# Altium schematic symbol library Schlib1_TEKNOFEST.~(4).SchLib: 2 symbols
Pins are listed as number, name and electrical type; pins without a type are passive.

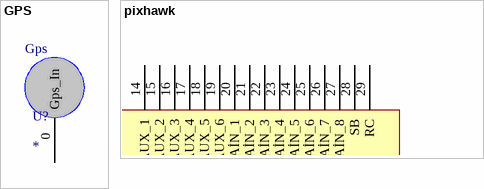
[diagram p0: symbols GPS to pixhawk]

## GPS
designator U?
pins: 0 Gps_In

## pixhawk
designator U?
pins: 0 SSR, 1 Switch, 2 Telem1, 3 Telem2, 4 USB, 5 SPI, 6 POWER, 7 BUZZER, 8 SERİAL 4/5, 9 GPS, 10 CAN, 11 I2C, 12 ADC3.3V, 13 ADC6.6V, 14 PWM AUX_1, 15 PWM AUX_2, 16 PWM AUX_3, 17 PWM AUX_4, 18 PWM AUX_5, 19 PWM AUX_6, 20 PWM MAİN_1, 21 PWM MAİN_2, 22 PWM MAİN_3, 23 PWM MAİN_4, 24 PWM MAİN_5, 25 PWM MAİN_6, 26 PWM MAİN_7, 27 PWM MAİN_8, 28 SB, 29 RC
